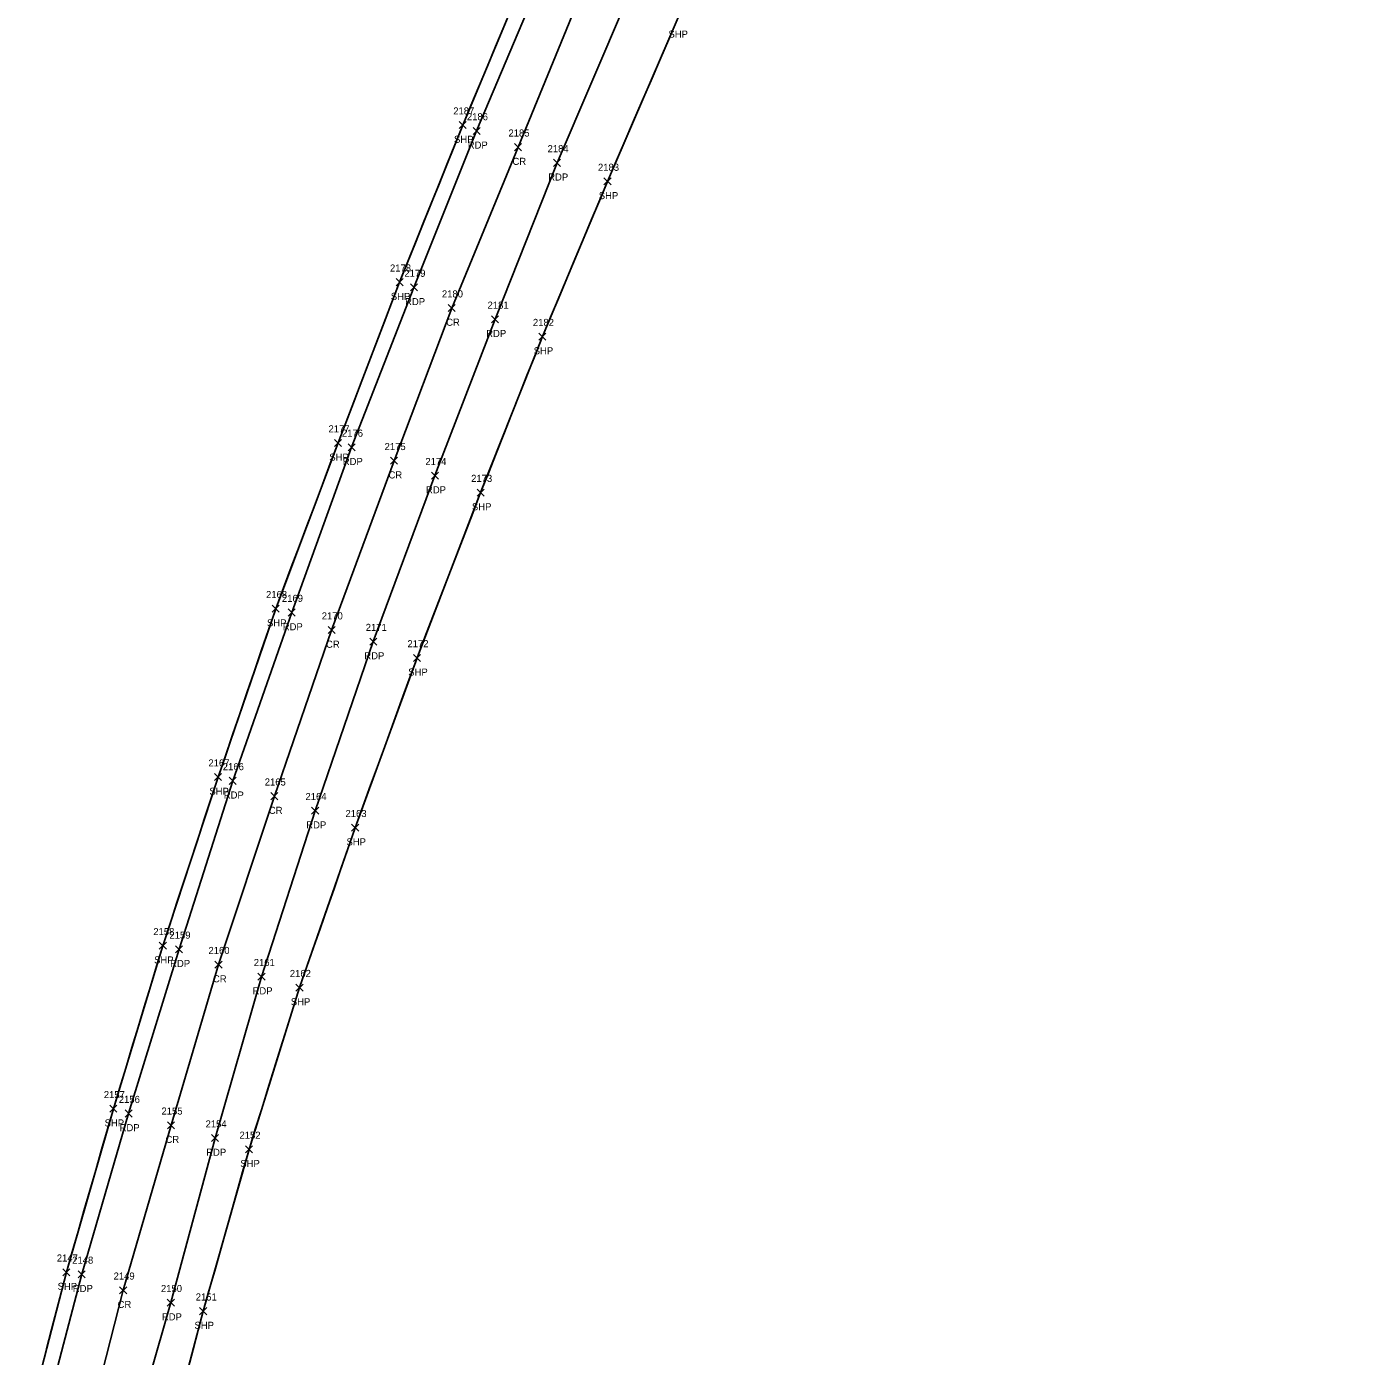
# Model space of a CAD drawing. Extents: x 1688195 to 1692013, y 424605 to 441234.
# Drawn here: x 1690771.1 to 1691151.2, y 437913 to 438288.1 of the extents above; entities that cross this region are included whole.
import ezdxf

# ---------------------------------------------------------------- set-up
doc = ezdxf.new("R2010")
doc.units = 0
for name, color, linetype in [('LSOGP', 7, 'Continuous'), ('P_A', 7, 'Continuous'), ('P_I', 7, 'Continuous'), ('P_TIC', 7, 'Continuous'), ('PET', 7, 'Continuous'), ('PRC', 7, 'Continuous'), ('PSP', 7, 'Continuous')]:
    doc.layers.add(name, color=color, linetype=linetype)

msp = doc.modelspace()

# ---------------------------------------------------------------- linework, layer by layer
at = {"layer": 'LSOGP'}
for points in [[(1690908.04, 438293.65), (1690905.73, 438288.11), (1690903.41, 438282.57), (1690901.1, 438277.03), (1690898.79, 438271.49), (1690896.47, 438265.95), (1690894.16, 438260.41), (1690891.93, 438254.87), (1690889.7, 438249.33), (1690887.46, 438243.79), (1690885.23, 438238.24), (1690883, 438232.7), (1690880.77, 438227.16), (1690878.54, 438221.61), (1690876.31, 438216.07), (1690874.14, 438210.4), (1690871.97, 438204.73), (1690869.8, 438199.06), (1690867.63, 438193.39), (1690865.46, 438187.72), (1690863.29, 438182.05), (1690861.12, 438176.38), (1690858.95, 438170.7), (1690856.75, 438164.86), (1690854.55, 438159.01), (1690852.35, 438153.16), (1690850.15, 438147.31), (1690847.95, 438141.46), (1690845.75, 438135.62), (1690843.55, 438129.77), (1690841.35, 438123.92), (1690839.32, 438117.98), (1690837.28, 438112.04), (1690835.25, 438106.09), (1690833.22, 438100.15), (1690831.18, 438094.21), (1690829.15, 438088.27), (1690827.12, 438082.32), (1690825.08, 438076.38), (1690823.13, 438070.43), (1690821.18, 438064.48), (1690819.23, 438058.53), (1690817.28, 438052.58), (1690815.33, 438046.63), (1690813.37, 438040.67), (1690811.42, 438034.72), (1690809.47, 438028.77), (1690807.72, 438023.02), (1690805.98, 438017.27), (1690804.23, 438011.52), (1690802.49, 438005.77), (1690800.74, 438000.02), (1690798.99, 437994.27), (1690797.25, 437988.52), (1690795.5, 437982.76), (1690793.84, 437977), (1690792.19, 437971.23), (1690790.53, 437965.46), (1690788.87, 437959.7), (1690787.21, 437953.93), (1690785.55, 437948.16), (1690783.89, 437942.4), (1690782.23, 437936.63), (1690780.84, 437931.22), (1690779.45, 437925.82), (1690778.06, 437920.42), (1690776.67, 437915.01), (1690775.27, 437909.61)], [(1690816.59, 437909.45), (1690818.02, 437914.85), (1690819.45, 437920.25), (1690820.87, 437925.64), (1690822.49, 437931.35), (1690824.11, 437937.06), (1690825.73, 437942.77), (1690827.34, 437948.47), (1690828.96, 437954.18), (1690830.58, 437959.89), (1690832.19, 437965.6), (1690833.81, 437971.31), (1690835.59, 437977.01), (1690837.38, 437982.72), (1690839.16, 437988.42), (1690840.94, 437994.13), (1690842.72, 437999.84), (1690844.51, 438005.54), (1690846.29, 438011.25), (1690848.07, 438016.96), (1690850.04, 438022.6), (1690852, 438028.24), (1690853.97, 438033.88), (1690855.93, 438039.53), (1690857.9, 438045.17), (1690859.86, 438050.81), (1690861.83, 438056.46), (1690863.79, 438062.1), (1690865.97, 438068.09), (1690868.15, 438074.08), (1690870.33, 438080.08), (1690872.51, 438086.07), (1690874.69, 438092.06), (1690876.87, 438098.05), (1690879.05, 438104.04), (1690881.24, 438110.03), (1690883.48, 438115.87), (1690885.73, 438121.7), (1690887.98, 438127.53), (1690890.22, 438133.37), (1690892.47, 438139.2), (1690894.72, 438145.03), (1690896.96, 438150.86), (1690899.21, 438156.7), (1690901.39, 438162.2), (1690903.57, 438167.7), (1690905.75, 438173.21), (1690907.93, 438178.71), (1690910.11, 438184.21), (1690912.29, 438189.71), (1690914.47, 438195.22), (1690916.65, 438200.72), (1690918.95, 438206.19), (1690921.25, 438211.67), (1690923.54, 438217.14), (1690925.84, 438222.61), (1690928.14, 438228.09), (1690930.43, 438233.56), (1690932.73, 438239.03), (1690935.03, 438244.51), (1690937.49, 438250.21), (1690939.95, 438255.91), (1690942.4, 438261.61), (1690944.86, 438267.31), (1690947.32, 438273.01), (1690949.78, 438278.71), (1690952.24, 438284.41), (1690954.7, 438290.11)]]:
    msp.add_lwpolyline(points, dxfattribs=at)
at = {"layer": 'P_TIC'}
for points in [[(1690893.16, 438259.41), (1690895.16, 438261.41)], [(1690895.16, 438259.41), (1690893.16, 438261.41)], [(1690897.07, 438257.78), (1690899.07, 438259.78)], [(1690899.07, 438257.78), (1690897.07, 438259.78)], [(1690908.76, 438253.18), (1690910.76, 438255.18)], [(1690910.76, 438253.18), (1690908.76, 438255.18)], [(1690919.79, 438248.76), (1690921.79, 438250.76)], [(1690921.79, 438248.76), (1690919.79, 438250.76)], [(1690934.03, 438243.51), (1690936.03, 438245.51)], [(1690936.03, 438243.51), (1690934.03, 438245.51)], [(1690875.31, 438215.07), (1690877.31, 438217.07)], [(1690877.31, 438215.07), (1690875.31, 438217.07)], [(1690879.38, 438213.59), (1690881.38, 438215.59)], [(1690881.38, 438213.59), (1690879.38, 438215.59)], [(1690890.05, 438207.77), (1690892.05, 438209.77)], [(1690892.05, 438207.77), (1690890.05, 438209.77)], [(1690902.29, 438204.6), (1690904.29, 438206.6)], [(1690904.29, 438204.6), (1690902.29, 438206.6)], [(1690915.65, 438199.72), (1690917.65, 438201.72)], [(1690917.65, 438199.72), (1690915.65, 438201.72)], [(1690857.95, 438169.7), (1690859.95, 438171.7)], [(1690859.95, 438169.7), (1690857.95, 438171.7)], [(1690861.79, 438168.47), (1690863.79, 438170.47)], [(1690863.79, 438168.47), (1690861.79, 438170.47)], [(1690873.77, 438164.68), (1690875.77, 438166.68)], [(1690875.77, 438164.68), (1690873.77, 438166.68)], [(1690885.3, 438160.47), (1690887.3, 438162.47)], [(1690887.3, 438160.47), (1690885.3, 438162.47)], [(1690898.21, 438155.7), (1690900.21, 438157.7)], [(1690900.21, 438155.7), (1690898.21, 438157.7)], [(1690840.35, 438122.92), (1690842.35, 438124.92)], [(1690842.35, 438122.92), (1690840.35, 438124.92)], [(1690844.85, 438121.83), (1690846.85, 438123.83)], [(1690846.85, 438121.83), (1690844.85, 438123.83)], [(1690856.12, 438116.88), (1690858.12, 438118.88)], [(1690858.12, 438116.88), (1690856.12, 438118.88)], [(1690867.89, 438113.64), (1690869.89, 438115.64)], [(1690869.89, 438113.64), (1690867.89, 438115.64)], [(1690880.24, 438109.03), (1690882.24, 438111.03)], [(1690882.24, 438109.03), (1690880.24, 438111.03)], [(1690824.08, 438075.38), (1690826.08, 438077.38)], [(1690826.08, 438075.38), (1690824.08, 438077.38)], [(1690828.21, 438074.33), (1690830.21, 438076.33)], [(1690830.21, 438074.33), (1690828.21, 438076.33)], [(1690839.98, 438070), (1690841.98, 438072)], [(1690841.98, 438070), (1690839.98, 438072)], [(1690851.48, 438065.89), (1690853.48, 438067.89)], [(1690853.48, 438065.89), (1690851.48, 438067.89)], [(1690862.79, 438061.1), (1690864.79, 438063.1)], [(1690864.79, 438061.1), (1690862.79, 438063.1)], [(1690808.47, 438027.77), (1690810.47, 438029.77)], [(1690810.47, 438027.77), (1690808.47, 438029.77)], [(1690813.04, 438026.77), (1690815.04, 438028.77)], [(1690815.04, 438026.77), (1690813.04, 438028.77)], [(1690824.18, 438022.45), (1690826.18, 438024.45)], [(1690826.18, 438022.45), (1690824.18, 438024.45)], [(1690836.32, 438019.05), (1690838.32, 438021.05)], [(1690838.32, 438019.05), (1690836.32, 438021.05)], [(1690847.07, 438015.96), (1690849.07, 438017.96)], [(1690849.07, 438015.96), (1690847.07, 438017.96)], [(1690794.5, 437981.76), (1690796.5, 437983.76)], [(1690796.5, 437981.76), (1690794.5, 437983.76)], [(1690798.79, 437980.42), (1690800.79, 437982.42)], [(1690800.79, 437980.42), (1690798.79, 437982.42)], [(1690810.79, 437977.12), (1690812.79, 437979.12)], [(1690812.79, 437977.12), (1690810.79, 437979.12)], [(1690823.23, 437973.49), (1690825.23, 437975.49)], [(1690825.23, 437973.49), (1690823.23, 437975.49)], [(1690832.81, 437970.31), (1690834.81, 437972.31)], [(1690834.81, 437970.31), (1690832.81, 437972.31)], [(1690781.23, 437935.63), (1690783.23, 437937.63)], [(1690783.23, 437935.63), (1690781.23, 437937.63)], [(1690785.57, 437935.04), (1690787.57, 437937.04)], [(1690787.57, 437935.04), (1690785.57, 437937.04)], [(1690797.27, 437930.55), (1690799.27, 437932.55)], [(1690799.27, 437930.55), (1690797.27, 437932.55)], [(1690810.72, 437927.04), (1690812.72, 437929.04)], [(1690812.72, 437927.04), (1690810.72, 437929.04)], [(1690819.87, 437924.64), (1690821.87, 437926.64)], [(1690821.87, 437924.64), (1690819.87, 437926.64)]]:
    msp.add_lwpolyline(points, dxfattribs=at)
at = {"layer": 'PET'}
for points in [[(1690775.14, 437892.19), (1690786.57, 437936.04), (1690799.79, 437981.42), (1690814.04, 438027.77), (1690829.21, 438075.33), (1690845.85, 438122.83), (1690862.79, 438169.47), (1690880.38, 438214.59), (1690898.07, 438258.78), (1690916.82, 438303.31), (1690937.83, 438351.19), (1690958.39, 438395.69), (1690978.22, 438436.78), (1690999.03, 438477.98), (1691023.05, 438523.63), (1691046.68, 438566.93), (1691075.12, 438616.57), (1691099.31, 438656.81)], [(1690799.47, 437885.38), (1690811.72, 437928.04), (1690824.23, 437974.49), (1690837.32, 438020.05), (1690852.48, 438066.89), (1690868.89, 438114.64), (1690886.3, 438161.47), (1690903.29, 438205.6), (1690920.79, 438249.76), (1690940.42, 438295.51), (1690961.06, 438342.34), (1690980.17, 438384.07), (1691003.87, 438423.28), (1691022.56, 438466.77), (1691049.18, 438510.29), (1691077.29, 438552.71), (1691107.39, 438594.95), (1691136, 438632.53)]]:
    msp.add_lwpolyline(points, dxfattribs=at)
at = {"layer": 'PRC'}
msp.add_lwpolyline([(1690787.43, 437889.13), (1690798.27, 437931.55), (1690811.79, 437978.12), (1690825.18, 438023.45), (1690840.98, 438071), (1690857.12, 438117.88), (1690874.77, 438165.68), (1690891.05, 438208.77), (1690909.76, 438254.18), (1690928.03, 438298.77), (1690949.8, 438346.77), (1690968.25, 438390.19), (1690989.69, 438431.53), (1691010.38, 438472.83), (1691033.68, 438517.29), (1691057.77, 438560.66), (1691085.08, 438608.78), (1691109.5, 438649.44)], dxfattribs=at)
at = {"layer": 'PSP'}
for points in [[(1690771.1, 437893.4), (1690782.23, 437936.63), (1690795.5, 437982.76), (1690809.47, 438028.77), (1690825.08, 438076.38), (1690841.35, 438123.92), (1690858.95, 438170.7), (1690876.31, 438216.07), (1690894.16, 438260.41), (1690912.67, 438304.72), (1690933.96, 438352.67), (1690954.51, 438396.96), (1690974.66, 438438.74), (1690995.63, 438479.86), (1691019.67, 438525.41), (1691043.09, 438568.57), (1691071.61, 438618.22), (1691095.76, 438658.57)], [(1690809.46, 437882.47), (1690820.87, 437925.64), (1690833.81, 437971.31), (1690848.07, 438016.96), (1690863.79, 438062.1), (1690881.24, 438110.03), (1690899.21, 438156.7), (1690916.65, 438200.72), (1690935.03, 438244.51), (1690954.7, 438290.11), (1690975.21, 438335.41), (1690995.71, 438376.63), (1691016.22, 438416.4), (1691039.98, 438458.65), (1691065.71, 438499.99), (1691093.5, 438542.86), (1691121.84, 438584.04), (1691151.19, 438621.79)]]:
    msp.add_lwpolyline(points, dxfattribs=at)

# ---------------------------------------------------------------- texts
at = {"layer": 'P_A'}
for s, p in [('SHP', (1690952.24, 438285.11)), ('SHP', (1690891.69, 438255.41)), ('RDP', (1690895.56, 438253.78)), ('CR', (1690908.19, 438249.18)), ('RDP', (1690918.28, 438244.76)), ('SHP', (1690932.56, 438239.51)), ('SHP', (1690873.84, 438211.07)), ('RDP', (1690877.87, 438209.59)), ('CR', (1690889.48, 438203.77)), ('RDP', (1690900.77, 438200.6)), ('SHP', (1690914.19, 438195.72)), ('SHP', (1690856.48, 438165.7)), ('RDP', (1690860.28, 438164.47)), ('CR', (1690873.2, 438160.68)), ('RDP', (1690883.78, 438156.47)), ('SHP', (1690896.75, 438151.7)), ('SHP', (1690838.88, 438118.92)), ('RDP', (1690843.33, 438117.83)), ('CR', (1690855.55, 438112.88)), ('RDP', (1690866.37, 438109.64)), ('SHP', (1690878.77, 438105.03)), ('SHP', (1690822.62, 438071.38)), ('RDP', (1690826.69, 438070.33)), ('CR', (1690839.41, 438066)), ('RDP', (1690849.97, 438061.89)), ('SHP', (1690861.33, 438057.1)), ('SHP', (1690807.01, 438023.77)), ('RDP', (1690811.53, 438022.77)), ('CR', (1690823.61, 438018.45)), ('RDP', (1690834.81, 438015.05)), ('SHP', (1690845.61, 438011.96)), ('SHP', (1690793.04, 437977.76)), ('RDP', (1690797.28, 437976.42)), ('CR', (1690810.22, 437973.12)), ('RDP', (1690821.72, 437969.49)), ('SHP', (1690831.35, 437966.31)), ('SHP', (1690779.77, 437931.63)), ('RDP', (1690784.06, 437931.04)), ('CR', (1690796.7, 437926.55)), ('RDP', (1690809.21, 437923.04)), ('SHP', (1690818.41, 437920.64))]:
    msp.add_text(s, height=2, dxfattribs=at).set_placement(p)
at = {"layer": 'P_I'}
for s, p in [('2187', (1690891.47, 438263.41)), ('2186', (1690895.32, 438261.78)), ('2185', (1690907.06, 438257.18)), ('2184', (1690918.1, 438252.76)), ('2183', (1690932.33, 438247.51)), ('2178', (1690873.61, 438219.07)), ('2179', (1690877.68, 438217.59)), ('2180', (1690888.27, 438211.77)), ('2181', (1690901.16, 438208.6)), ('2182', (1690913.96, 438203.72)), ('2177', (1690856.25, 438173.7)), ('2176', (1690860.04, 438172.47)), ('2175', (1690872.08, 438168.68)), ('2174', (1690883.6, 438164.47)), ('2173', (1690896.52, 438159.7)), ('2168', (1690838.61, 438126.92)), ('2169', (1690843.1, 438125.83)), ('2170', (1690854.34, 438120.88)), ('2171', (1690866.76, 438117.64)), ('2172', (1690878.54, 438113.03)), ('2167', (1690822.34, 438079.38)), ('2166', (1690826.41, 438078.33)), ('2165', (1690838.24, 438074)), ('2164', (1690849.74, 438069.89)), ('2163', (1690861.05, 438065.1)), ('2158', (1690806.78, 438031.77)), ('2159', (1690811.34, 438030.77)), ('2160', (1690822.35, 438026.45)), ('2161', (1690835.14, 438023.05)), ('2162', (1690845.33, 438019.96)), ('2157', (1690792.81, 437985.76)), ('2156', (1690797.04, 437984.42)), ('2155', (1690809.09, 437981.12)), ('2154', (1690821.54, 437977.49)), ('2152', (1690831.12, 437974.31)), ('2147', (1690779.54, 437939.63)), ('2148', (1690783.88, 437939.04)), ('2149', (1690795.57, 437934.55)), ('2150', (1690808.94, 437931.04)), ('2151', (1690818.75, 437928.64))]:
    msp.add_text(s, height=2, dxfattribs=at).set_placement(p)

doc.saveas('drawing.dxf')
